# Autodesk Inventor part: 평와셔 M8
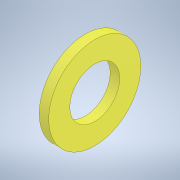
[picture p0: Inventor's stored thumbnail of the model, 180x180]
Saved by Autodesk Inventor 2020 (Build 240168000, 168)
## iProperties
Created: 2024-04
Part Number: 평와셔 M8
Material: 강철, 연강
Description: 평면 와셔
Document SubType Name: Modeling
Designer: oem
Density: 7.86 g/cm^3
Appearance: 기본값
Author: jhkim
Sending System: Autodesk Inventor 2025
Preprocessor: ST-DEVELOPER v20
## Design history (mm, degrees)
feature "Solid1"
node "솔리드1"
